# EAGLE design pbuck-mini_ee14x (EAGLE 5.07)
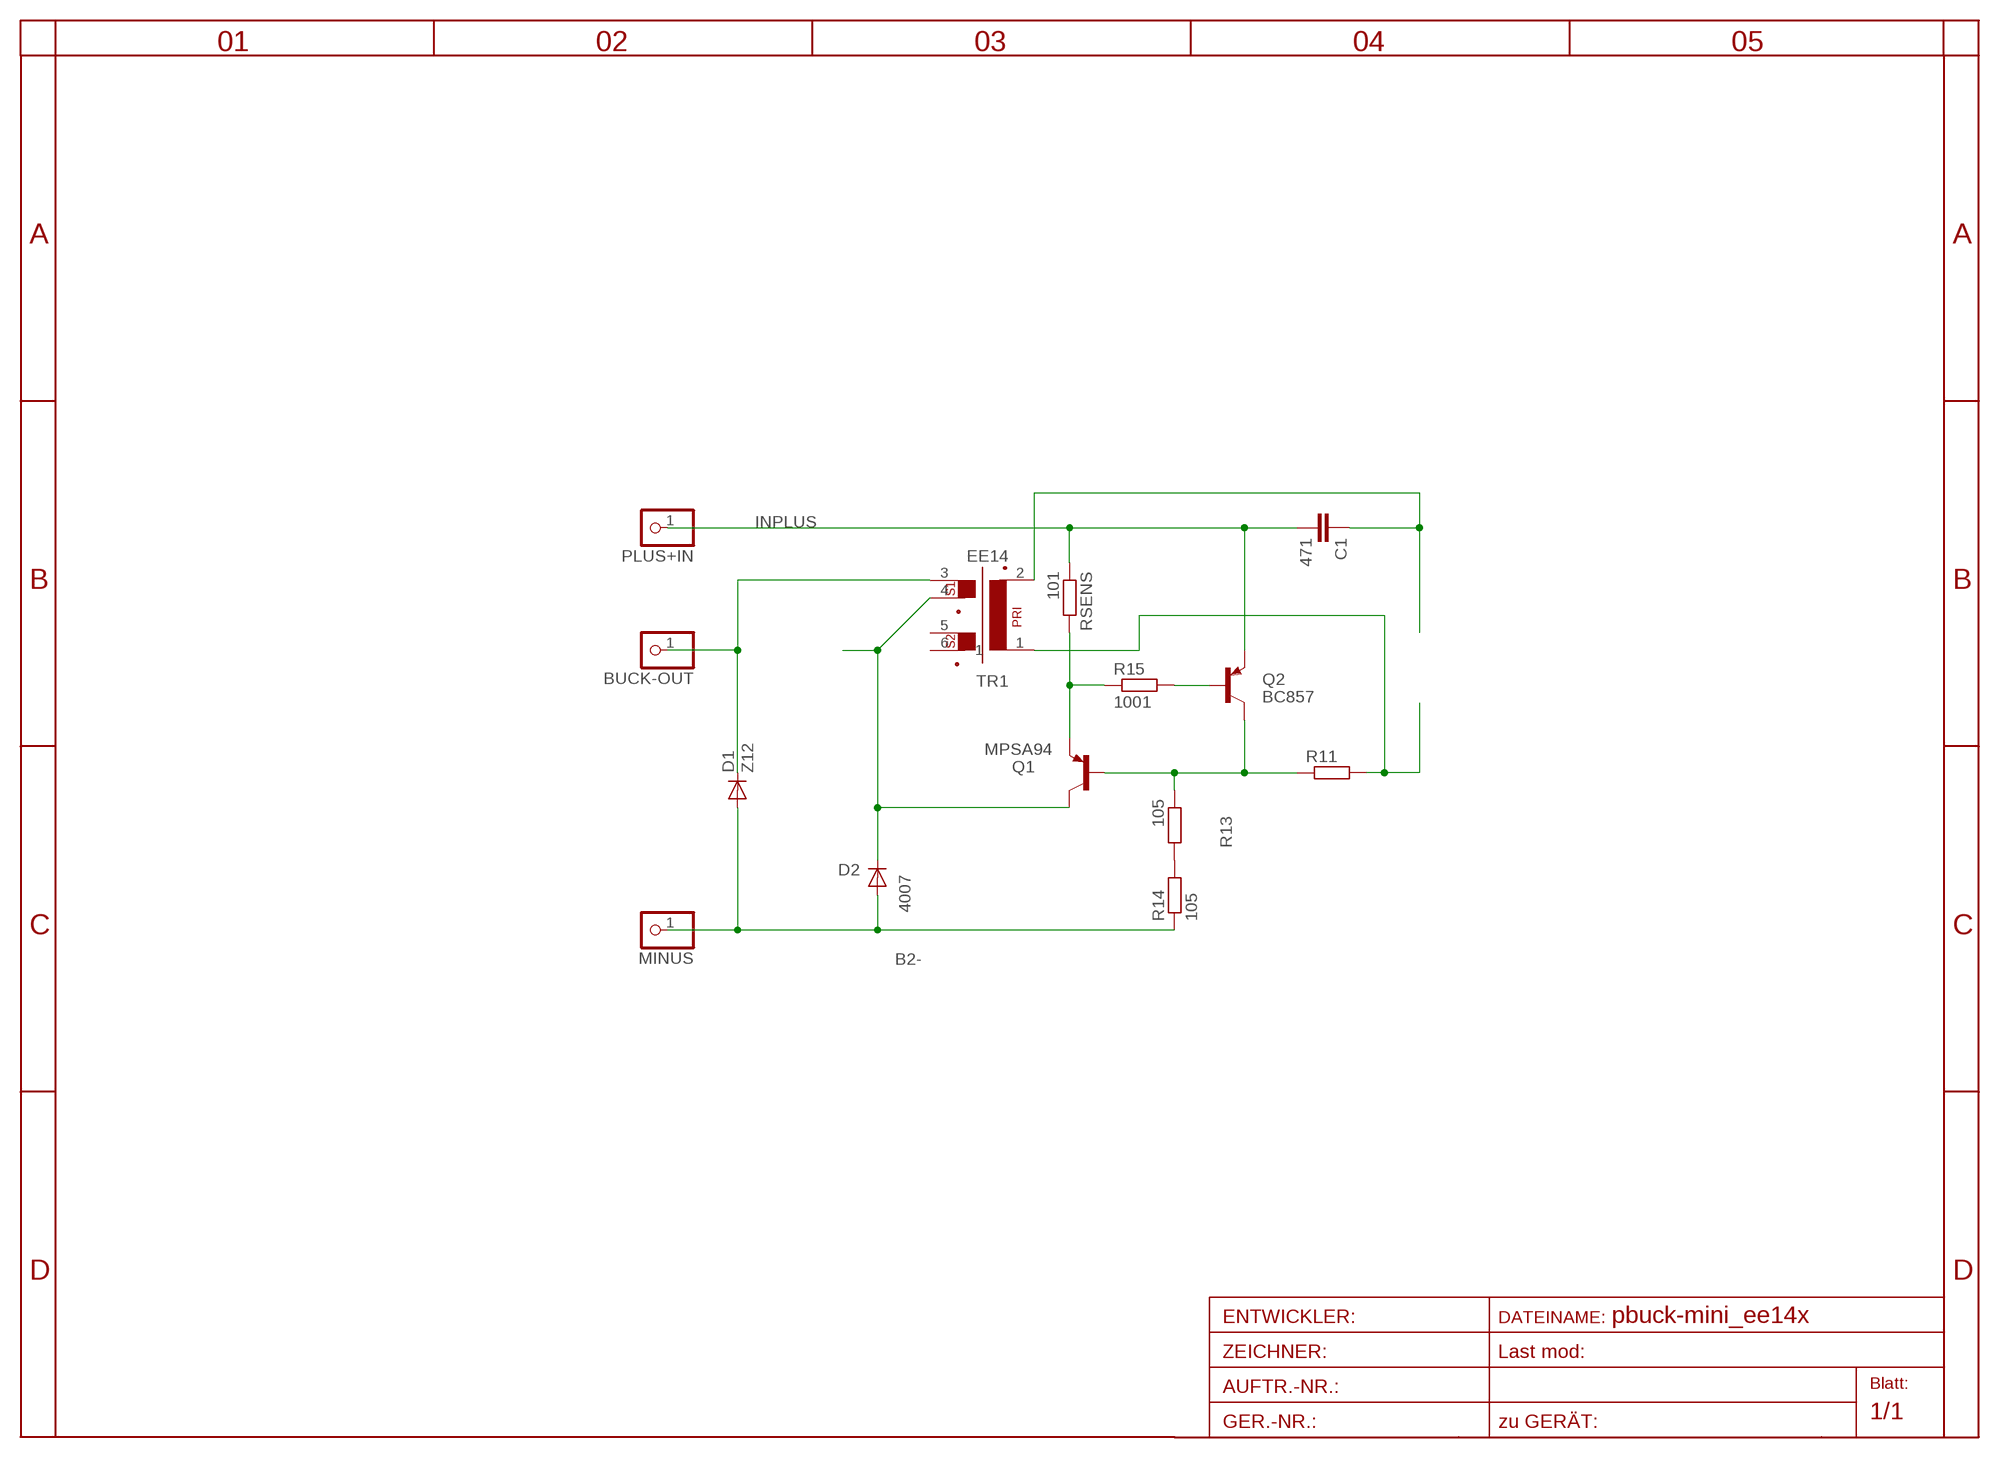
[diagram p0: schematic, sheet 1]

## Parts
BUCK-OUT  PINHD-1X11MM0  [1X1MM0]
C1  471  C-EUC0805  [C0805]
D1  Z12  DIODE-MINIMELF  [MINIMELF]
D2  4007  DIODE-SMA-DO214  [SMA-DO214AC]
MINUS  PINHD-1X11MM0  [1X1MM0]
PLUS+IN  PINHD-1X11MM0  [1X1MM0]
Q1  MPSA94  MPSW92  [TO92-CBE]
Q2  BC857  BC857ALT1SMD  [SOT23-BEC]
R11  R-EU_R0805  [R0805]
R13  105  R-EU_R1206  [R1206]
R14  105  R-EU_R1206  [R1206]
R15  1001  R-EU_R1206  [R1206]
RSENS  101  R-EU_R1206  [R1206]
TR1  EE14  EE14EE14  [EE14]

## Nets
B2-: D1.A D2.A MINUS.1 R14.1
B92: Q1.B Q2.C R11.1 R13.1
B_OUT: BUCK-OUT.1 D1.C TR1.3
C92: D2.K(C) Q1.C TR1.4
EB: Q1.E R15.1 RSENS.2
INPLUS: C1.2 PLUS+IN.1 Q2.E RSENS.1
L4DOT: C1.1 TR1.2
L4NO: R11.2 TR1.1
N$11: R13.2 R14.2
N$12: Q2.B R15.2
Unconnected: TR1.5 TR1.6

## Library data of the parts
BUCK-OUT MINUS PLUS+IN = pinhead:PINHD-1X1: PIN HEADER
C1 = rcl:C-EU: CAPACITOR, European symbol
D1 D2 = diode:DIODE-: DIODE
Q1 = transistor-pnp:MPSW92*: PNP Transistror
Q2 = transistor-pnp:BC857*: PNP Transistror
R11 R13-R15 RSENS = rcl:R-EU_: RESISTOR, European symbol
TR1 = trafo:EE14

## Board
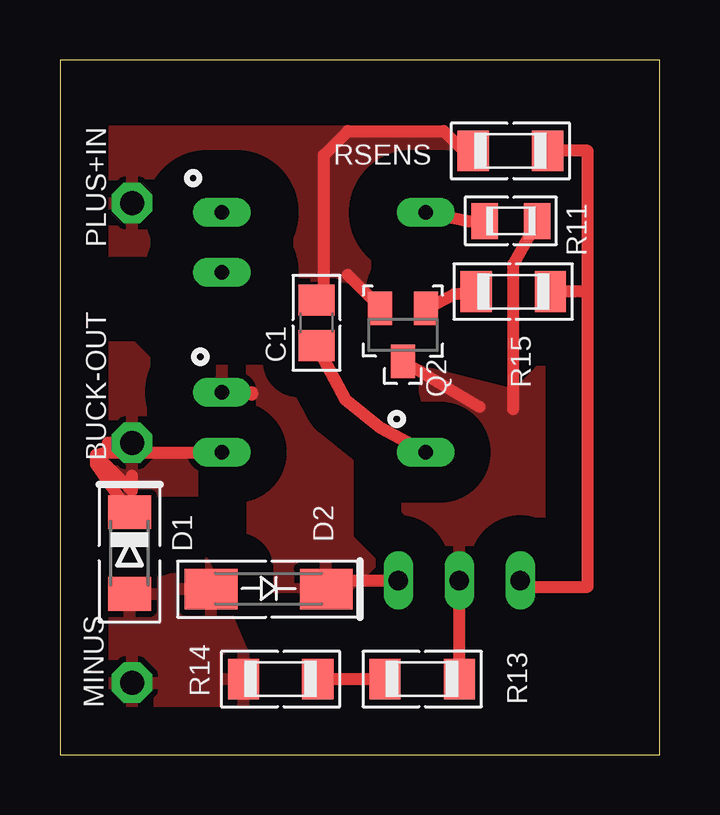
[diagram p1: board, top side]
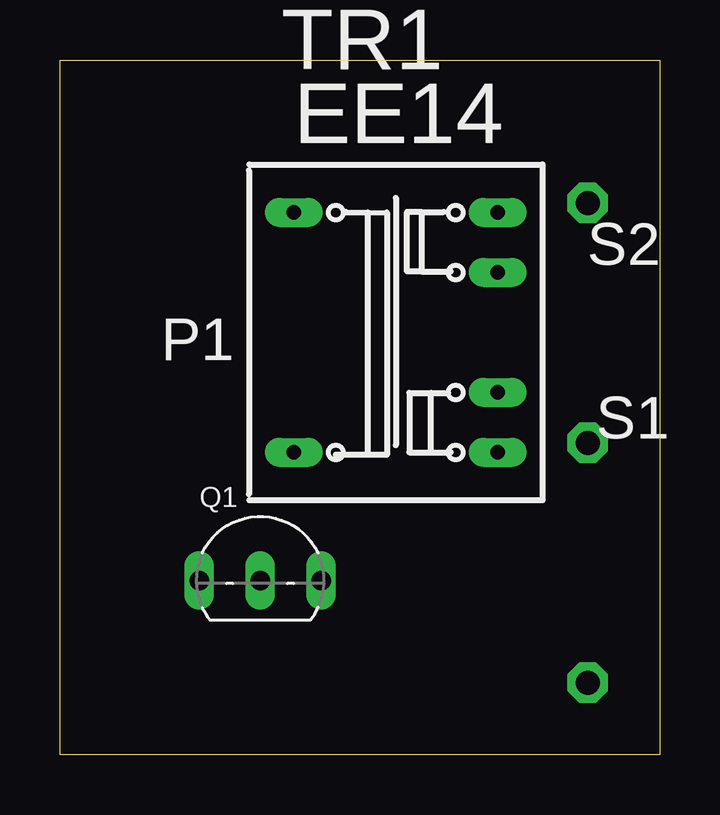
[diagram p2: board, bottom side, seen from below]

Size 25 x 28.96 mm. Coordinates in mm from the lower left corner, seen from the top.
Outline: 0,0 25,0 25,28.96 0,28.96 0,0
Copper layers (1*16): Top 0.035mm / dielectric 1.5mm / Bottom 0.035mm
Design rules "default *": minimum track width 10mil, minimum drill 20mil, track to track 8mil, track to pad 8mil, pad to pad 8mil, via to via 8mil, smd to smd 8mil, copper to edge 2mm, drill to drill 8mil, minimum pad ring 8mil, minimum via ring 8mil, stop-mask expansion 4mil, vias tented up to drill 0mil, thermal gap 10mil

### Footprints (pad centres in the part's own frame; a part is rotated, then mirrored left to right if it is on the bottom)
1X1MM0 = drill 1 pad 1.676 octagon: 1 0,0
C0805 = smd 1.3 x 1.5: 1 -0.95,0; 2 0.95,0
MINIMELF = smd 1.4 x 1.8: A 1.7,0; C -1.7,0
SMA-DO214AC = smd 2.2 x 1.7: A 2.4,0; K -2.4,0
TO92-CBE = drill 0.813 long: B 0,0; C 2.54,0; E -2.54,0
SOT23-BEC = smd 1 x 1.4: B -0.95,-1.1; C 0,1.1; E 0.95,-1.1
R0805 = smd 1.1 x 1.5: 1 -1.1,0; 2 1.1,0
R1206 = smd 1.3 x 1.7: 1 -1.55,0; 2 1.55,0
EE14 = drill 0.6 pad 1.2 long: 1 4.25,-5; 2 4.25,5; 3 -4.25,5; 4 -4.25,2.5; 5 -4.25,-2.5; 6 -4.25,-5

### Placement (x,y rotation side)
BUCK-OUT  3,13 0 top
C1  10.7,18 90 top
D1  2.9,8.4 270 top
D2  8.7,6.9 180 top
MINUS  3,3 0 top
PLUS+IN  3,23 0 top
Q1  16.65,7.26 0 bottom
Q2  14.3,17.5 180 top
R11  18.8,22.25 180 top
R13  15.1,3.15 180 top
R14  9.2,3.15 0 top
R15  18.9,19.3 180 top
RSENS  18.78,25.17 0 top
TR1  11,17.6 180 bottom

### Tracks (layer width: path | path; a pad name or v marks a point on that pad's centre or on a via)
B2-
  pour Top (isolate 2, rank 2): 2,8 6,8 9,1 2,1
B92
  Top 0.5: Q2.C 17.5,14.5 | R11.1 18.9,20.45 18.9,14.4 | R13.1 Q1.B
  pour Top (isolate 1.5, rank 3): 15,16 19,15 20,16 22,16 22,10 21,8 15,8 14,7 13,7 13,10 14,10 16,12
B_OUT
  Top 0.406: TR1.3 5.75,12.63
  Top 0.5: 3,11.63 3,11 1.5,12.5 | 1.5,12.5 BUCK-OUT.1 2,13 2,12.6 TR1.3 | D1.C 1.5,12.1 1.5,12.5
  pour Top (isolate 2, rank 4): 2,17 3,17 9,11 2,11
C92
  Top 0.5: Q1.C 11,7.26 11,7 11.1,7 D2.K | TR1.4 8,15.1 8,15
  pour Top (isolate 1.5, rank 2): 6,16 6,14 8,12 8,7 12,7 13,8 12,9 12,13 9,16
EB
  Top 0.5: RSENS.2 22,25.17 22,19.3 | Q1.E 19.19,7 22,7 22,19.3 | 22,19.3 R15.1
INPLUS
  Top 0.5: RSENS.1 17.23,24.77 16,26 12,26 11,25 11,19.25 C1.2 | Q2.E 13.35,18.65 12,20
  pour Top (isolate 2): 2,26 16,26 16,17 11,17 8,22 7,21 2,21
L4DOT
  Top 0.406: 14.4,12.6 TR1.2
  Top 0.5: TR1.2 13.4,13.6 11.9,14.8 C1.1
L4NO
  Top 0.406: TR1.1 14.25,22.58
  Top 0.5: R11.2 16.95,22.25 TR1.1
N$11
  Top 0.5: R14.2 R13.2
N$12
  Top 0.5: R15.2 16.45,19.2 Q2.B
